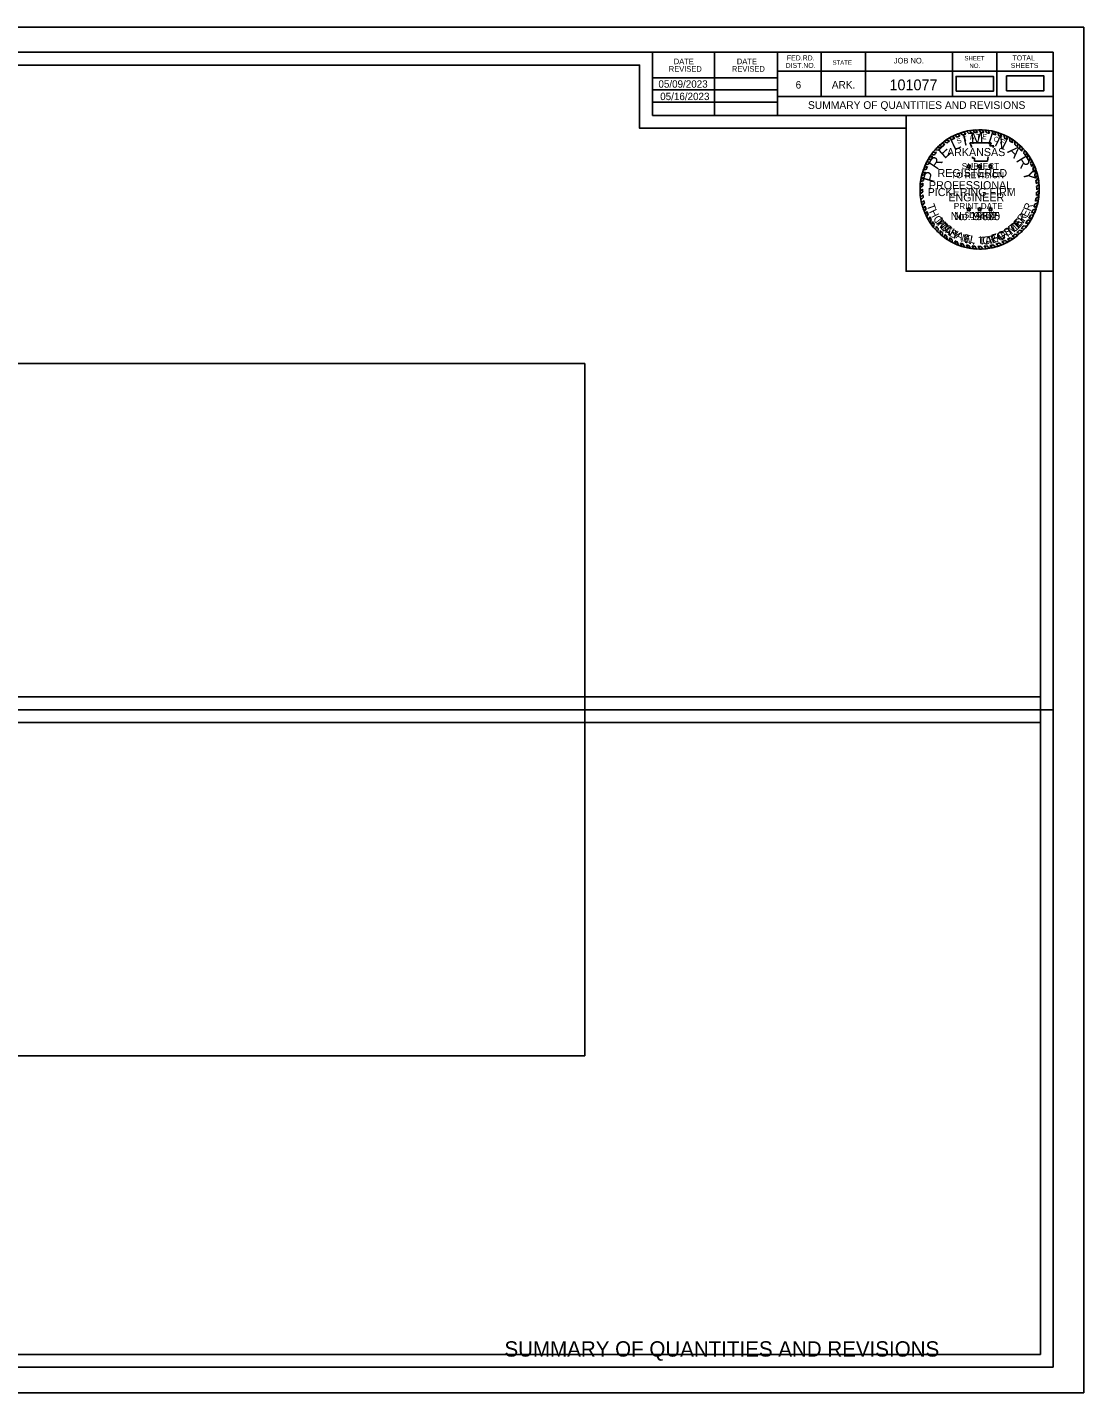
# Model space of a CAD drawing. Extents: x 1369655 to 1370989, y 380216 to 380430.
# Drawn here: x 1370823.5 to 1370988.6, y 380216.4 to 380429.8 of the extents above; entities that cross this region are included whole.
import ezdxf

# ---------------------------------------------------------------- set-up
doc = ezdxf.new("R2010")
doc.units = 0
for name, color, linetype in [('Default', 7, 'Continuous'), ('R_Border', 7, 'Continuous'), ('R_Border Notes', 7, 'Continuous'), ('R_Border Plan-Plan', 7, 'Continuous'), ('R_Border Title', 7, 'Continuous'), ('R_No Plot', 7, 'Continuous'), ('R_Revision Date Text', 7, 'Continuous'), ('STAMP_PE_CRAFTON', 7, 'Continuous'), ('STAMP_PE_FOSTER', 7, 'Continuous'), ('STAMP_PE_SEAL-INFO', 7, 'Continuous'), ('STAMP_PE_TAEGTMEYER', 7, 'Continuous'), ('STAMP_PE_TXT', 7, 'Continuous'), ('STAMP_PRELIMINARY', 7, 'Continuous')]:
    doc.layers.add(name, color=color, linetype=linetype)

msp = doc.modelspace()

# ---------------------------------------------------------------- linework, layer by layer
at = {"layer": 'Default'}
for points in [[(1370968.65, 380419.77), (1370974.49, 380419.77), (1370974.49, 380422.08), (1370968.65, 380422.08)], [(1370976.54, 380419.86), (1370982.37, 380419.86), (1370982.37, 380422.17), (1370976.54, 380422.17)], [(1370740.86, 380269.06), (1370910.63, 380269.06), (1370910.63, 380377.22), (1370740.86, 380377.22)]]:
    msp.add_lwpolyline(points, close=True, dxfattribs=at)
at = {"layer": 'R_Border'}
for p, q in [((1370667.65, 380425.87), (1370983.83, 380425.87)), ((1370921.19, 380415.99), (1370921.19, 380425.87)), ((1370930.87, 380415.99), (1370930.87, 380425.87)), ((1370940.73, 380425.87), (1370940.73, 380415.99)), ((1370947.57, 380425.87), (1370947.57, 380418.93)), ((1370954.51, 380425.87), (1370954.51, 380418.93)), ((1370968.09, 380425.87), (1370968.09, 380418.93)), ((1370975.03, 380425.87), (1370975.03, 380418.93)), ((1370983.83, 380220.41), (1370983.83, 380425.87)), ((1370921.19, 380421.85), (1370940.73, 380421.85)), ((1370983.83, 380422.93), (1370940.73, 380422.93)), ((1370983.83, 380422.95), (1370983.83, 380422.95)), ((1370921.19, 380419.99), (1370940.73, 380419.99)), ((1370921.19, 380418.05), (1370940.73, 380418.05)), ((1370983.83, 380418.93), (1370940.73, 380418.93)), ((1370943.69, 380418.93), (1370983.83, 380418.93)), ((1370983.83, 380415.99), (1370921.19, 380415.99)), ((1370983.83, 380220.41), (1370667.65, 380220.41))]:
    msp.add_line(p, q, dxfattribs=at)
at = {"layer": 'R_Border Plan-Plan'}
msp.add_line((1370667.65, 380323.14), (1370983.83, 380323.14), dxfattribs=at)
at = {"layer": 'R_No Plot'}
for points in [[(1370655.25, 380429.76), (1370988.59, 380429.76), (1370988.59, 380216.42), (1370655.25, 380216.42)], [(1370981.83, 380325.14), (1370669.65, 380325.14), (1370669.65, 380423.87), (1370919.19, 380423.87), (1370919.19, 380413.99), (1370936.73, 380413.99), (1370960.83, 380413.99), (1370960.83, 380391.65), (1370981.83, 380391.65)], [(1370669.65, 380423.87), (1370919.19, 380423.87), (1370919.19, 380413.99), (1370936.73, 380413.99), (1370960.83, 380413.99), (1370960.83, 380391.65), (1370981.83, 380391.65), (1370981.83, 380222.41), (1370669.65, 380222.41)], [(1370960.83, 380415.99), (1370983.83, 380415.99), (1370983.83, 380391.65), (1370960.83, 380391.65)], [(1370669.65, 380321.14), (1370981.83, 380321.14), (1370981.83, 380222.41), (1370669.65, 380222.41)]]:
    msp.add_lwpolyline(points, close=True, dxfattribs=at)
at = {"layer": 'STAMP_PE_SEAL-INFO'}
for p, q in [((1370968.95, 380413.12), (1370969.24, 380412.79)), ((1370969.29, 380413.24), (1370969.67, 380412.94)), ((1370969.88, 380413.43), (1370970.17, 380413.08)), ((1370970.27, 380413.52), (1370970.63, 380413.18)), ((1370970.75, 380413.62), (1370971.05, 380413.25)), ((1370971.27, 380413.69), (1370971.55, 380413.31)), ((1370972.01, 380413.34), (1370971.69, 380413.73)), ((1370972.5, 380413.34), (1370972.22, 380413.75)), ((1370972.96, 380413.32), (1370972.7, 380413.75)), ((1370973.47, 380413.27), (1370973.18, 380413.71)), ((1370973.89, 380413.21), (1370973.64, 380413.66)), ((1370974.46, 380413.09), (1370974.28, 380413.55)), ((1370974.86, 380412.98), (1370974.7, 380413.45)), ((1370975.31, 380412.83), (1370975.17, 380413.31)), ((1370975.73, 380412.67), (1370975.58, 380413.17)), ((1370976.19, 380412.47), (1370976.09, 380412.96)), ((1370965.7, 380410.98), (1370966.24, 380410.93)), ((1370966.03, 380411.3), (1370966.49, 380411.16)), ((1370966.37, 380411.6), (1370966.9, 380411.5)), ((1370966.75, 380411.93), (1370967.21, 380411.72)), ((1370967.17, 380412.19), (1370967.61, 380411.99)), ((1370967.56, 380412.44), (1370967.99, 380412.21)), ((1370968.01, 380412.69), (1370968.47, 380412.46)), ((1370968.44, 380412.9), (1370968.83, 380412.62)), ((1370970.81, 380411.72), (1370974.15, 380411.72)), ((1370970.93, 380411.41), (1370970.81, 380411.72)), ((1370971.03, 380411.12), (1370970.93, 380411.41)), ((1370971.04, 380411), (1370971.03, 380411.12)), ((1370974.15, 380411.72), (1370973.93, 380411.23)), ((1370973.93, 380411.23), (1370974.56, 380411.23)), ((1370974.56, 380411.23), (1370974.41, 380411)), ((1370976.63, 380412.24), (1370976.55, 380412.75)), ((1370977.02, 380412.01), (1370976.98, 380412.51)), ((1370977.46, 380411.72), (1370977.42, 380412.24)), ((1370977.82, 380411.46), (1370977.85, 380411.94)), ((1370978.26, 380411.09), (1370978.28, 380411.61)), ((1370978.58, 380410.79), (1370978.65, 380411.29)), ((1370978.93, 380410.42), (1370979, 380410.95)), ((1370964.04, 380408.68), (1370964.54, 380408.75)), ((1370964.27, 380409.11), (1370964.76, 380409.13)), ((1370964.51, 380409.51), (1370965.03, 380409.54)), ((1370964.75, 380409.85), (1370965.25, 380409.85)), ((1370965.03, 380410.22), (1370965.58, 380410.24)), ((1370965.37, 380410.63), (1370965.89, 380410.59)), ((1370971.23, 380409.29), (1370971.2, 380409.51)), ((1370971.54, 380409.29), (1370971.23, 380409.29)), ((1370971.54, 380408.86), (1370971.54, 380409.29)), ((1370973.57, 380408.86), (1370971.54, 380408.86)), ((1370973.59, 380409.2), (1370973.57, 380408.86)), ((1370973.67, 380409.51), (1370973.59, 380409.2)), ((1370979.21, 380410.1), (1370979.35, 380410.57)), ((1370979.53, 380409.69), (1370979.67, 380410.19)), ((1370979.75, 380409.37), (1370979.93, 380409.83)), ((1370980.06, 380408.87), (1370980.24, 380409.36)), ((1370980.26, 380408.51), (1370980.49, 380408.95)), ((1370963.25, 380406.54), (1370963.72, 380406.74)), ((1370963.36, 380406.95), (1370963.84, 380407.12)), ((1370963.52, 380407.45), (1370964, 380407.59)), ((1370963.67, 380407.86), (1370964.17, 380408.01)), ((1370963.85, 380408.29), (1370964.35, 380408.4)), ((1370980.49, 380408.02), (1370980.72, 380408.51)), ((1370980.63, 380407.69), (1370980.9, 380408.12)), ((1370980.83, 380407.14), (1370981.1, 380407.61)), ((1370980.93, 380406.77), (1370981.23, 380407.22)), ((1370981.07, 380406.21), (1370981.39, 380406.66)), ((1370963.44, 380404.98), (1370963.02, 380404.72)), ((1370963.42, 380404.49), (1370963.02, 380404.15)), ((1370963.47, 380405.4), (1370963.04, 380405.12)), ((1370963.53, 380405.84), (1370963.09, 380405.62)), ((1370963.62, 380406.3), (1370963.15, 380406.05)), ((1370981.14, 380405.83), (1370981.49, 380406.19)), ((1370981.2, 380405.32), (1370981.57, 380405.66)), ((1370981.23, 380404.91), (1370981.62, 380405.2)), ((1370981.25, 380404.39), (1370981.65, 380404.71)), ((1370963.43, 380404.08), (1370963.04, 380403.75)), ((1370963.46, 380403.58), (1370963.09, 380403.23)), ((1370963.51, 380403.15), (1370963.16, 380402.78)), ((1370963.59, 380402.69), (1370963.25, 380402.33)), ((1370963.68, 380402.28), (1370963.37, 380401.86)), ((1370980.95, 380402.14), (1370981.42, 380402.34)), ((1370981.06, 380402.59), (1370981.51, 380402.78)), ((1370981.15, 380403.09), (1370981.59, 380403.31)), ((1370981.2, 380403.48), (1370981.63, 380403.73)), ((1370981.24, 380403.98), (1370981.66, 380404.26)), ((1370963.81, 380401.83), (1370963.51, 380401.41)), ((1370963.95, 380401.41), (1370963.67, 380400.99)), ((1370964.12, 380400.98), (1370963.85, 380400.56)), ((1370964.29, 380400.6), (1370964.06, 380400.13)), ((1370980.29, 380400.41), (1370980.78, 380400.48)), ((1370980.45, 380400.75), (1370980.94, 380400.84)), ((1370980.67, 380401.26), (1370981.15, 380401.39)), ((1370980.8, 380401.64), (1370981.29, 380401.84)), ((1370964.52, 380400.14), (1370964.33, 380399.65)), ((1370964.76, 380399.73), (1370964.57, 380399.26)), ((1370964.96, 380399.42), (1370964.85, 380398.87)), ((1370965.24, 380399.03), (1370965.14, 380398.5)), ((1370965.54, 380398.65), (1370965.46, 380398.13)), ((1370965.85, 380398.32), (1370965.79, 380397.79)), ((1370978.56, 380398.05), (1370979, 380397.91)), ((1370978.82, 380398.31), (1370979.29, 380398.23)), ((1370979.2, 380398.74), (1370979.66, 380398.67)), ((1370979.51, 380399.14), (1370980.01, 380399.14)), ((1370979.85, 380399.63), (1370980.32, 380399.63)), ((1370980.02, 380399.91), (1370980.52, 380399.97)), ((1370966.17, 380397.99), (1370966.14, 380397.46)), ((1370966.51, 380397.68), (1370966.51, 380397.15)), ((1370966.87, 380397.38), (1370966.89, 380396.86)), ((1370967.21, 380397.13), (1370967.25, 380396.62)), ((1370967.64, 380396.85), (1370967.7, 380396.34)), ((1370967.99, 380396.65), (1370968.08, 380396.13)), ((1370968.47, 380396.4), (1370968.63, 380395.88)), ((1370968.84, 380396.23), (1370969.02, 380395.72)), ((1370969.34, 380396.04), (1370969.55, 380395.53)), ((1370969.75, 380395.9), (1370969.97, 380395.41)), ((1370974.89, 380395.89), (1370975.3, 380395.59)), ((1370975.38, 380396.05), (1370975.82, 380395.78)), ((1370975.8, 380396.22), (1370976.22, 380395.96)), ((1370976.26, 380396.43), (1370976.74, 380396.22)), ((1370976.67, 380396.64), (1370977.08, 380396.41)), ((1370977.08, 380396.89), (1370977.53, 380396.69)), ((1370977.42, 380397.11), (1370977.86, 380396.92)), ((1370977.88, 380397.46), (1370978.35, 380397.31)), ((1370978.16, 380397.68), (1370978.63, 380397.55)), ((1370970.25, 380395.76), (1370970.47, 380395.3)), ((1370970.65, 380395.68), (1370970.9, 380395.22)), ((1370971.15, 380395.6), (1370971.39, 380395.16)), ((1370971.59, 380395.55), (1370971.86, 380395.12)), ((1370972.07, 380395.52), (1370972.38, 380395.11)), ((1370972.53, 380395.52), (1370972.88, 380395.12)), ((1370973.05, 380395.55), (1370973.38, 380395.17)), ((1370973.49, 380395.59), (1370973.86, 380395.23)), ((1370973.93, 380395.66), (1370974.32, 380395.32)), ((1370974.43, 380395.77), (1370974.8, 380395.44))]:
    msp.add_line(p, q, dxfattribs=at)
for radius, start, end in [(9.32, 111.3124, 114.7026), (9.32, 105.2339, 109.0352), (8.91, 104.0352, 107.3615), (9.32, 99.7525, 102.7765), (8.91, 98.258, 101.0329), (9.32, 93.9381, 96.5517), (8.91, 92.1102, 95.0367), (9.32, 87.7298, 90.6707), (8.91, 85.9628, 88.9097), (9.32, 81.9732, 84.8236), (8.91, 79.9264, 82.696), (9.32, 75.3125, 77.9426), (8.91, 73.5575, 76.2314), (9.32, 69.6061, 72.3058), (9.32, 63.1329, 66.2704), (9.32, 135.4021, 138.3031), (8.91, 133.1331, 136.2562), (9.32, 129.7326, 132.5376), (8.91, 127.5297, 130.9683), (9.32, 123.6199, 126.5906), (8.91, 121.9746, 125.11), (9.32, 117.6544, 120.8099), (8.91, 115.6869, 119.1583), (8.91, 110.3086, 113.1659), (8.91, 67.6248, 70.504), (8.91, 61.1558, 64.3784), (9.32, 56.9003, 60.0942), (8.91, 54.9238, 58.2702), (8.91, 48.3016, 52.0395), (9.32, 50.3492, 53.7159), (9.32, 44.3405, 47.3929), (9.32, 152.864, 155.5189), (9.32, 147.0072, 149.899), (8.91, 151.0315, 153.573), (9.32, 141.6056, 144.4486), (8.91, 145.0197, 148.2104), (8.91, 139.301, 142.5873), (8.91, 42.2212, 45.5512), (8.91, 36.135, 39.5311), (9.32, 38.1247, 41.2316), (8.91, 29.9032, 33.6645), (9.32, 31.9614, 35.4294), (9.32, 25.9391, 29.0125), (9.32, 164.3068, 166.894), (9.32, 158.4077, 161.0701), (8.91, 162.4331, 165.0013), (8.91, 156.3402, 159.2319), (8.91, 23.7732, 27.2211), (8.91, 17.6802, 21.4251), (9.32, 19.9538, 23.3141), (8.91, 11.5444, 15.2364), (9.32, 13.8421, 17.4447), (9.32, 175.7409, 178.2066), (9.32, 170.0003, 172.6878), (8.91, 179.6454, 182.2633), (8.91, 173.73, 176.4734), (8.91, 167.9048, 170.9039), (8.91, 5.7599, 9.0606), (8.91, 359.7329, 3.0639), (9.32, 7.5852, 10.8621), (9.32, 1.7215, 4.7268), (9.32, 181.7251, 184.1626), (9.32, 187.4204, 190.1927), (9.32, 193.0369, 195.9973), (8.91, 185.4539, 188.234), (8.91, 191.2274, 193.9858), (8.91, 348.0778, 351.3435), (8.91, 353.8632, 357.1274), (9.32, 343.8925, 347.035), (9.32, 349.8305, 353.0885), (9.32, 355.7156, 358.9569), (9.32, 198.8967, 201.6281), (8.91, 196.9675, 199.8353), (9.32, 204.5479, 207.4328), (8.91, 202.7761, 205.4791), (8.91, 329.5549, 333.2076), (8.91, 335.6038, 339.1858), (9.32, 331.4037, 334.9332), (8.91, 341.777, 345.0925), (9.32, 337.3837, 340.9933), (9.32, 210.8636, 213.6571), (8.91, 208.7883, 211.7934), (9.32, 216.6115, 219.491), (8.91, 214.1838, 217.2747), (9.32, 222.48, 225.3801), (8.91, 220.3909, 223.3056), (8.91, 310.7744, 314.3161), (8.91, 316.6531, 320.3711), (9.32, 318.2846, 321.8043), (8.91, 323.5851, 327.4407), (9.32, 325.4405, 328.9872), (9.32, 228.3665, 231.348), (8.91, 226.2494, 229.2407), (8.91, 232.229, 234.9336), (9.32, 234.295, 236.9452), (8.91, 238.2223, 240.8353), (9.32, 240.1977, 242.8613), (8.91, 244.3204, 246.9486), (9.32, 246.576, 249.1558), (8.91, 250.3491, 253.1216), (8.91, 286.6423, 289.9783), (8.91, 292.8745, 296.1185), (9.32, 294.6481, 298.2166), (8.91, 299.0768, 302.1724), (9.32, 300.621, 303.8703), (8.91, 304.823, 308.5143), (9.32, 306.3721, 310.208), (9.32, 312.4518, 315.6633), (9.32, 252.5967, 255.3252), (8.91, 256.505, 259.1192), (9.32, 258.4433, 261.1398), (8.91, 262.3783, 265.2012), (9.32, 264.1978, 267.1009), (8.91, 268.3215, 271.277), (9.32, 270.2548, 273.3361), (8.91, 274.6157, 277.4486), (9.32, 276.4239, 279.4357), (8.91, 280.3459, 283.5814), (9.32, 282.3199, 285.3702), (9.32, 288.5709, 291.9733)]:
    msp.add_arc((1370972.33, 380404.43), radius, start, end, dxfattribs=at)
at = {"layer": 'STAMP_PE_TXT'}
for p, q in [((1370970.51, 380408), (1370970.31, 380408.15)), ((1370970.31, 380408.15), (1370970.56, 380408.15)), ((1370970.44, 380407.77), (1370970.51, 380408)), ((1370970.64, 380407.91), (1370970.44, 380407.77)), ((1370970.56, 380408.15), (1370970.64, 380408.38)), ((1370970.64, 380408.38), (1370970.71, 380408.15)), ((1370970.83, 380407.77), (1370970.64, 380407.91)), ((1370970.71, 380408.15), (1370970.96, 380408.15)), ((1370970.96, 380408.15), (1370970.76, 380408)), ((1370970.76, 380408), (1370970.83, 380407.77)), ((1370972.21, 380408), (1370972.01, 380408.15)), ((1370972.01, 380408.15), (1370972.26, 380408.15)), ((1370972.14, 380407.77), (1370972.21, 380408)), ((1370972.33, 380407.91), (1370972.14, 380407.77)), ((1370972.26, 380408.15), (1370972.33, 380408.38)), ((1370972.33, 380408.38), (1370972.41, 380408.15)), ((1370972.53, 380407.77), (1370972.33, 380407.91)), ((1370972.41, 380408.15), (1370972.65, 380408.15)), ((1370972.65, 380408.15), (1370972.46, 380408)), ((1370972.46, 380408), (1370972.53, 380407.77)), ((1370973.91, 380408), (1370973.71, 380408.15)), ((1370973.71, 380408.15), (1370973.96, 380408.15)), ((1370973.83, 380407.77), (1370973.91, 380408)), ((1370974.03, 380407.91), (1370973.83, 380407.77)), ((1370973.96, 380408.15), (1370974.03, 380408.38)), ((1370974.03, 380408.38), (1370974.11, 380408.15)), ((1370974.23, 380407.77), (1370974.03, 380407.91)), ((1370974.11, 380408.15), (1370974.35, 380408.15)), ((1370974.35, 380408.15), (1370974.15, 380408)), ((1370974.15, 380408), (1370974.23, 380407.77)), ((1370970.51, 380401.29), (1370970.31, 380401.44)), ((1370970.31, 380401.44), (1370970.56, 380401.44)), ((1370970.44, 380401.06), (1370970.51, 380401.29)), ((1370970.64, 380401.21), (1370970.44, 380401.06)), ((1370970.56, 380401.44), (1370970.64, 380401.67)), ((1370970.64, 380401.67), (1370970.71, 380401.44)), ((1370970.83, 380401.06), (1370970.64, 380401.21)), ((1370970.71, 380401.44), (1370970.96, 380401.44)), ((1370970.96, 380401.44), (1370970.76, 380401.29)), ((1370970.76, 380401.29), (1370970.83, 380401.06)), ((1370972.21, 380401.29), (1370972.01, 380401.44)), ((1370972.01, 380401.44), (1370972.26, 380401.44)), ((1370972.14, 380401.06), (1370972.21, 380401.29)), ((1370972.33, 380401.21), (1370972.14, 380401.06)), ((1370972.26, 380401.44), (1370972.33, 380401.67)), ((1370972.33, 380401.67), (1370972.41, 380401.44)), ((1370972.53, 380401.06), (1370972.33, 380401.21)), ((1370972.41, 380401.44), (1370972.65, 380401.44)), ((1370972.65, 380401.44), (1370972.46, 380401.29)), ((1370972.46, 380401.29), (1370972.53, 380401.06)), ((1370973.91, 380401.29), (1370973.71, 380401.44)), ((1370973.71, 380401.44), (1370973.96, 380401.44)), ((1370973.83, 380401.06), (1370973.91, 380401.29)), ((1370974.03, 380401.21), (1370973.83, 380401.06)), ((1370973.96, 380401.44), (1370974.03, 380401.67)), ((1370974.03, 380401.67), (1370974.11, 380401.44)), ((1370974.23, 380401.06), (1370974.03, 380401.21)), ((1370974.11, 380401.44), (1370974.35, 380401.44)), ((1370974.35, 380401.44), (1370974.15, 380401.29)), ((1370974.15, 380401.29), (1370974.23, 380401.06))]:
    msp.add_line(p, q, dxfattribs=at)
at = {"layer": 'STAMP_PRELIMINARY'}
msp.add_circle((1370972.33, 380404.43), 9.32, dxfattribs=at)

# ---------------------------------------------------------------- texts
at = {"layer": 'R_Border'}
for s, height, p in [('REVISED', 0.879, (1370923.75, 380422.82)), ('DATE', 0.879, (1370924.53, 380424)), ('REVISED', 0.879, (1370933.61, 380422.82)), ('DATE', 0.879, (1370934.39, 380424)), ('DIST.NO.', 0.782, (1370942.01, 380423.41)), ('FED.RD.', 0.782, (1370942.21, 380424.59)), ('STATE', 0.684, (1370949.33, 380423.91)), ('JOB NO.', 0.879, (1370958.91, 380424.11)), ('SHEET', 0.684, (1370969.95, 380424.59)), ('NO.', 0.684, (1370970.73, 380423.41)), ('SHEETS', 0.782, (1370977.19, 380423.41)), ('TOTAL', 0.782, (1370977.47, 380424.59)), ('6', 1.17, (1370943.57, 380420.19)), ('ARK.', 1.172, (1370949.23, 380420.19))]:
    msp.add_text(s, height=height, dxfattribs=at).set_placement(p)
at = {"layer": 'R_Border Notes'}
for s, height, p in [('101077', 1.68, (1370958.24, 380419.93)), ('SUMMARY OF QUANTITIES AND REVISIONS', 1.2, (1370945.5, 380417.01))]:
    msp.add_text(s, height=height, dxfattribs=at).set_placement(p)
at = {"layer": 'R_Border Title'}
msp.add_text('SUMMARY OF QUANTITIES AND REVISIONS', height=2.4, dxfattribs=at).set_placement((1370898.07, 380222.06))
at = {"layer": 'R_Revision Date Text'}
for s, p in [('05/09/2023', (1370922.13, 380420.33)), ('05/16/2023', (1370922.41, 380418.39))]:
    msp.add_text(s, height=1.15, dxfattribs=at).set_placement(p)
at = {"layer": 'STAMP_PE_CRAFTON'}
msp.add_text('No. 12370', height=1.25, dxfattribs=at).set_placement((1370967.8, 380399.63))
for s, rotation, p in [('T', 310.7442, (1370965.3, 380399.33)), ('O', 317.6422, (1370965.97, 380398.52)), ('N', 324.4537, (1370966.81, 380397.73)), ('Y', 331.1686, (1370967.85, 380397.02)), ('F', 28.7821, (1370975.99, 380396.56)), ('T', 34.1136, (1370976.91, 380397.07)), ('O', 41.8391, (1370977.77, 380397.67)), ('N', 49.2411, (1370978.62, 380398.45)), ('N', 347.4752, (1370969.9, 380396.1)), ('.', 356.8926, (1370971.13, 380395.82)), ('C', 6.0117, (1370972.81, 380395.77)), ('R', 14.8189, (1370973.9, 380395.89)), ('A', 20.5125, (1370975.01, 380396.19))]:
    msp.add_text(s, height=1.25, rotation=rotation, dxfattribs=at).set_placement(p)
at = {"layer": 'STAMP_PE_FOSTER'}
msp.add_text('No. 9402', height=1.25, dxfattribs=at).set_placement((1370968.32, 380399.63))
for s, rotation, p in [('R', 54.5031, (1370979.06, 380399.24)), ('M', 308.339, (1370965.45, 380399.45)), ('I', 314.1842, (1370966.25, 380398.51)), ('C', 319.8733, (1370966.6, 380398.16)), ('H', 327.7235, (1370967.53, 380397.42)), ('S', 31.7234, (1370976.52, 380397.04)), ('T', 39.4194, (1370977.48, 380397.67)), ('E', 46.9613, (1370978.33, 380398.42)), ('A', 335.7276, (1370968.51, 380396.84)), ('E', 343.5779, (1370969.65, 380396.37)), ('L', 350.8115, (1370970.71, 380396.1)), ('L', 1.2666, (1370972.25, 380395.94)), ('.', 6.8035, (1370973.29, 380396)), ('F', 15.8691, (1370974.37, 380396.18)), ('O', 23.719, (1370975.41, 380396.51))]:
    msp.add_text(s, height=1.2, rotation=rotation, dxfattribs=at).set_placement(p)
at = {"layer": 'STAMP_PE_TAEGTMEYER'}
for s, rotation, p in [('T', 289.646, (1370964.03, 380401.94)), ('R', 69.57, (1370980.28, 380400.94)), ('H', 296.7339, (1370964.39, 380400.96)), ('O', 303.7708, (1370964.98, 380399.85)), ('Y', 53.9986, (1370979.11, 380399.02)), ('E', 63.0984, (1370979.78, 380399.96)), ('M', 314.2033, (1370965.64, 380398.9)), ('A', 321.0594, (1370966.6, 380397.93)), ('S', 327.8239, (1370967.42, 380397.29)), ('T', 31.466, (1370976.43, 380396.78)), ('M', 39.3, (1370977.33, 380397.33)), ('E', 46.8094, (1370978.37, 380398.21)), ('N', 344.2727, (1370969.32, 380396.28)), ('.', 350.6464, (1370970.53, 380395.95)), ('T', 3.0061, (1370972.2, 380395.75)), ('A', 8.9826, (1370973.24, 380395.81)), ('E', 17.6836, (1370974.28, 380395.96)), ('G', 23.3052, (1370975.33, 380396.29))]:
    msp.add_text(s, height=1.25, rotation=rotation, dxfattribs=at).set_placement(p)
msp.add_text('No. 19605', height=1.25, dxfattribs=at).set_placement((1370967.8, 380399.63))
at = {"layer": 'STAMP_PE_TXT'}
for s, rotation, p in [('A', 9.0679, (1370970.82, 380412.16)), ('T', 1.8248, (1370971.8, 380412.29)), ('E', 355.2002, (1370972.71, 380412.3)), ('S', 23.5541, (1370968.93, 380411.53)), ('T', 16.311, (1370969.86, 380411.91)), ('O', 342.2506, (1370974.44, 380412.02)), ('F', 335.0075, (1370975.41, 380411.68))]:
    msp.add_text(s, height=0.781, rotation=rotation, dxfattribs=at).set_placement(p)
for s, p in [('ARKANSAS', (1370967.23, 380409.64)), ('REGISTERED', (1370965.75, 380406.37)), ('PROFESSIONAL', (1370964.4, 380404.47)), ('ENGINEER', (1370967.44, 380402.57))]:
    msp.add_text(s, height=1.25, dxfattribs=at).set_placement(p)
at = {"layer": 'STAMP_PRELIMINARY'}
for s, rotation, p in [('I', 12.5248, (1370969.87, 380411.22)), ('M', 3.1074, (1370970.97, 380411.53)), ('I', 342.3164, (1370973.44, 380411.59)), ('E', 42.3578, (1370966.86, 380409.13)), ('L', 25.513, (1370968.34, 380410.46)), ('N', 333.9382, (1370974.54, 380411.32)), ('A', 315.6579, (1370976.58, 380410.29)), ('R', 56.2292, (1370965.7, 380407.39)), ('R', 301.3831, (1370977.95, 380408.98)), ('P', 73.913, (1370965.16, 380405.37)), ('Y', 283.2593, (1370979.04, 380407.19))]:
    msp.add_text(s, height=1.8, rotation=rotation, dxfattribs=at).set_placement(p)
for s, height, p in [('TO REVISION', 0.96, (1370967.87, 380406.19)), ('SUBJECT', 0.96, (1370969.53, 380407.58)), ('PICKERING FIRM', 1.25, (1370964.21, 380403.39)), ('PRINT DATE', 0.96, (1370968.29, 380401.35)), ('$DATE$', 0.96, (1370969.97, 380399.96))]:
    msp.add_text(s, height=height, dxfattribs=at).set_placement(p)

doc.saveas('drawing.dxf')
